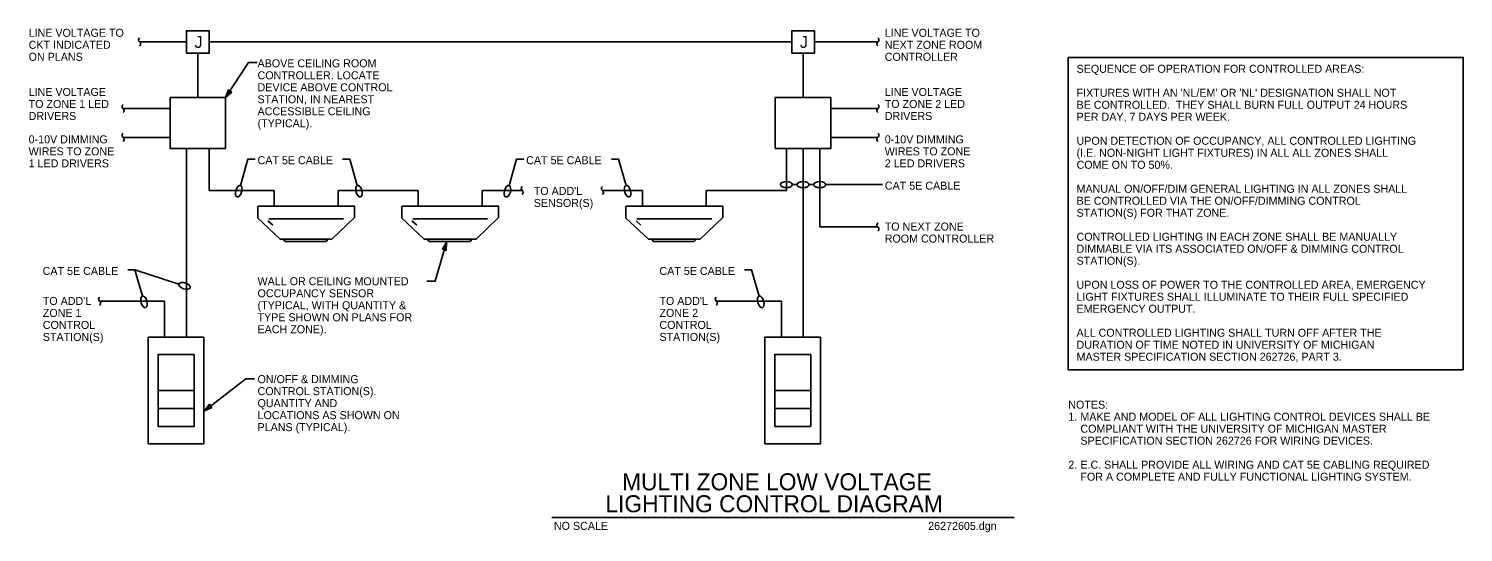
# Model space of a CAD drawing. Extents: x 10121 to 10241, y 10006 to 10048.
import ezdxf

# ---------------------------------------------------------------- set-up
doc = ezdxf.new("R2010")
doc.units = 0
for name, color, linetype in [('G-ANNO-CELL', 7, 'Continuous'), ('G-ANNO-TEXT', 7, 'Continuous'), ('G-DETL-LINE', 7, 'Continuous'), ('Level 3', 7, 'Continuous')]:
    doc.layers.add(name, color=color, linetype=linetype)

msp = doc.modelspace()

# ---------------------------------------------------------------- linework, layer by layer
at = {"layer": 'G-ANNO-CELL'}
msp.add_line((10164.75, 10007.02), (10203.28, 10007.02), dxfattribs=at)
at = {"layer": 'G-ANNO-TEXT'}
for p, q in [((10185.19, 10034.77), (10184.8, 10034.77)), ((10186.58, 10034.77), (10186.19, 10034.77)), ((10192.3, 10034.77), (10187.58, 10034.77)), ((10130.03, 10027.66), (10133.68, 10026.48))]:
    msp.add_line(p, q, dxfattribs=at)
for points in [[(10207.78, 10045.37), (10240.69, 10045.37), (10240.69, 10019.34), (10207.78, 10019.34)], [(10138.09, 10042.49), (10137.58, 10042.03), (10137.82, 10042.67)], [(10155.64, 10029.39), (10155.99, 10029.98), (10155.96, 10029.29)], [(10136.44, 10016.2), (10135.81, 10015.92), (10136.23, 10016.46)]]:
    msp.add_lwpolyline(points, close=True, dxfattribs=at)
for points in [[(10140.21, 10044.94), (10139.48, 10044.94), (10137.58, 10042.03)], [(10140.03, 10036.89), (10139.43, 10036.89), (10138.81, 10034.7)], [(10147.33, 10036.89), (10147.93, 10036.89), (10148.55, 10034.7)], [(10162.41, 10036.89), (10161.81, 10036.89), (10161.19, 10034.7)], [(10169.72, 10036.89), (10170.32, 10036.89), (10170.94, 10034.7)], [(10154.33, 10026.73), (10155.04, 10026.73), (10155.99, 10029.98)], [(10129.42, 10027.66), (10130.03, 10027.66), (10130.65, 10025.47)], [(10180.8, 10027.66), (10181.4, 10027.66), (10182.02, 10025.47)], [(10139.98, 10018.58), (10139.25, 10018.58), (10135.81, 10015.92)]]:
    msp.add_lwpolyline(points, dxfattribs=at)
for centre, major_axis in [((10138.67, 10034.22), (-0.136, -0.481)), ((10148.69, 10034.22), (0.136, -0.481)), ((10161.06, 10034.22), (-0.136, -0.481)), ((10171.07, 10034.22), (0.136, -0.481)), ((10184.3, 10034.77), (-0.5, 0)), ((10185.69, 10034.77), (-0.5, 0)), ((10187.08, 10034.77), (-0.5, 0)), ((10134.16, 10026.33), (0.476, -0.153)), ((10130.78, 10024.99), (0.136, -0.481)), ((10182.16, 10024.99), (0.136, -0.481))]:
    msp.add_ellipse(centre, major_axis=major_axis, ratio=0.5, dxfattribs=at)
at = {"layer": 'G-DETL-LINE'}
for p, q in [((10134.32, 10046.66), (10130.41, 10046.66)), ((10184.75, 10046.66), (10136.2, 10046.66)), ((10186.63, 10046.66), (10191.92, 10046.66)), ((10135.26, 10042.03), (10135.26, 10045.72)), ((10185.69, 10042.03), (10185.69, 10045.72)), ((10132.95, 10041.11), (10129.03, 10041.11)), ((10188.01, 10041.11), (10191.92, 10041.11)), ((10132.95, 10038.71), (10129.03, 10038.71)), ((10188.01, 10038.71), (10191.92, 10038.71)), ((10134.31, 10022.05), (10134.31, 10037.79)), ((10136.21, 10034.29), (10136.21, 10037.79)), ((10184.3, 10034.29), (10184.3, 10037.79)), ((10185.69, 10022.05), (10185.69, 10037.79)), ((10187.08, 10031.24), (10187.08, 10037.79)), ((10136.21, 10034.29), (10141.62, 10034.29)), ((10141.62, 10032.97), (10141.62, 10034.29)), ((10146.95, 10032.97), (10146.95, 10034.29)), ((10146.95, 10034.29), (10153.62, 10034.29)), ((10153.62, 10032.97), (10153.62, 10034.29)), ((10158.95, 10032.97), (10158.95, 10034.29)), ((10162.29, 10034.29), (10158.95, 10034.29)), ((10168.96, 10034.29), (10172.3, 10034.29)), ((10172.3, 10032.97), (10172.3, 10034.29)), ((10177.62, 10034.29), (10184.3, 10034.29)), ((10177.62, 10032.97), (10177.62, 10034.29)), ((10141.5, 10031.38), (10141.1, 10031.74)), ((10141.17, 10031.92), (10144.29, 10031.92)), ((10147.41, 10031.92), (10144.29, 10031.92)), ((10153.5, 10031.38), (10153.1, 10031.74)), ((10153.17, 10031.92), (10156.29, 10031.92)), ((10159.41, 10031.92), (10156.29, 10031.92)), ((10172.17, 10031.38), (10171.77, 10031.74)), ((10171.84, 10031.92), (10174.96, 10031.92)), ((10178.08, 10031.92), (10174.96, 10031.92)), ((10191.92, 10031.24), (10187.08, 10031.24)), ((10132.5, 10025.05), (10127.08, 10025.05)), ((10132.5, 10022.05), (10132.5, 10025.05)), ((10183.88, 10025.05), (10178.46, 10025.05)), ((10183.88, 10022.05), (10183.88, 10025.05)), ((10134.95, 10016.11), (10131.95, 10016.11)), ((10186.33, 10016.11), (10183.33, 10016.11))]:
    msp.add_line(p, q, dxfattribs=at)
for points in [[(10134.32, 10045.72), (10134.32, 10047.6), (10136.2, 10047.6), (10136.2, 10045.72)], [(10184.75, 10045.72), (10184.75, 10047.6), (10186.63, 10047.6), (10186.63, 10045.72)], [(10132.95, 10042.03), (10137.58, 10042.03), (10137.58, 10037.79), (10132.95, 10037.79)], [(10188.01, 10042.03), (10183.37, 10042.03), (10183.37, 10037.79), (10188.01, 10037.79)], [(10135.77, 10022.05), (10131.14, 10022.05), (10131.14, 10013.17), (10135.77, 10013.17)], [(10187.15, 10022.05), (10182.51, 10022.05), (10182.51, 10013.17), (10187.15, 10013.17)], [(10134.95, 10020.61), (10131.95, 10020.61), (10131.95, 10017.61), (10134.95, 10017.61)], [(10186.33, 10020.61), (10183.33, 10020.61), (10183.33, 10017.61), (10186.33, 10017.61)], [(10134.95, 10017.61), (10131.95, 10017.61), (10131.95, 10014.61), (10134.95, 10014.61)], [(10186.33, 10017.61), (10183.33, 10017.61), (10183.33, 10014.61), (10186.33, 10014.61)]]:
    msp.add_lwpolyline(points, close=True, dxfattribs=at)
for points in [[(10140.26, 10032.97), (10148.32, 10032.97), (10148.32, 10032.03), (10146.44, 10030.23), (10142.12, 10030.23), (10140.26, 10031.98), (10140.26, 10032.97)], [(10152.26, 10032.97), (10160.32, 10032.97), (10160.32, 10032.03), (10158.44, 10030.23), (10154.12, 10030.23), (10152.26, 10031.98), (10152.26, 10032.97)], [(10170.93, 10032.97), (10178.99, 10032.97), (10178.99, 10032.03), (10177.11, 10030.23), (10172.8, 10030.23), (10170.93, 10031.98), (10170.93, 10032.97)], [(10146.09, 10030.23), (10146.09, 10030.17), (10145.93, 10030.02), (10142.56, 10030.02), (10142.41, 10030.17), (10142.41, 10030.23)], [(10158.09, 10030.23), (10158.09, 10030.17), (10157.93, 10030.02), (10154.56, 10030.02), (10154.41, 10030.17), (10154.41, 10030.23)], [(10176.76, 10030.23), (10176.76, 10030.17), (10176.6, 10030.02), (10173.24, 10030.02), (10173.08, 10030.17), (10173.08, 10030.23)]]:
    msp.add_lwpolyline(points, dxfattribs=at)
for centre, start, end in [((10130.54, 10046.83), 126.8699, 233.1301), ((10130.29, 10046.5), 306.8699, 53.1301), ((10192.05, 10046.5), 126.8699, 233.1301), ((10191.8, 10046.83), 306.8699, 53.1301), ((10129.16, 10041.27), 126.8699, 233.1301), ((10128.91, 10040.94), 306.8699, 53.1301), ((10192.05, 10040.94), 126.8699, 233.1301), ((10191.8, 10041.27), 306.8699, 53.1301), ((10129.16, 10038.88), 126.8699, 233.1301), ((10128.91, 10038.54), 306.8699, 53.1301), ((10192.05, 10038.54), 126.8699, 233.1301), ((10191.8, 10038.88), 306.8699, 53.1301), ((10162.41, 10034.45), 126.8699, 233.1301), ((10169.09, 10034.45), 126.8699, 233.1301), ((10162.16, 10034.12), 306.8699, 53.1301), ((10168.84, 10034.12), 306.8699, 53.1301), ((10192.05, 10031.41), 126.8699, 233.1301), ((10191.8, 10031.07), 306.8699, 53.1301), ((10127.21, 10025.22), 126.8699, 233.1301), ((10126.96, 10024.88), 306.8699, 53.1301), ((10178.58, 10025.22), 126.8699, 233.1301), ((10178.33, 10024.88), 306.8699, 53.1301)]:
    msp.add_arc(centre, 0.208, start, end, dxfattribs=at)

# ---------------------------------------------------------------- texts
at = {"layer": 'G-ANNO-CELL'}
for s, height, p in [('MULTI ZONE LOW VOLTAGE', 1.4167, (10170.61, 10009.29)), ('LIGHTING CONTROL DIAGRAM', 1.4167, (10169.22, 10007.46)), ('NO SCALE', 0.667, (10164.93, 10005.99))]:
    msp.add_text(s, height=height, dxfattribs=at).set_placement(p)
at = {"layer": 'G-ANNO-TEXT'}
for s, height, p in [('LINE VOLTAGE TO ', 0.6667, (10121.17, 10047.09)), ('LINE VOLTAGE TO ', 0.6667, (10192.49, 10047.09)), ('CKT INDICATED ', 0.6667, (10121.17, 10046.09)), ('NEXT ZONE ROOM ', 0.6667, (10192.49, 10046.09)), ('ON PLANS', 0.667, (10121.17, 10045.09)), ('CONTROLLER', 0.667, (10192.49, 10045.09)), ('ABOVE CEILING ROOM ', 0.6667, (10140.24, 10044.55)), ('CONTROLLER. LOCATE ', 0.6667, (10140.24, 10043.55)), ('SEQUENCE OF OPERATION FOR CONTROLLED AREAS:', 0.6667, (10208.47, 10044.09)), ('DEVICE ABOVE CONTROL ', 0.6667, (10140.24, 10042.55)), ('TO ZONE 1 LED ', 0.6667, (10121.17, 10041.16)), ('LINE VOLTAGE ', 0.6667, (10121.17, 10042.16)), ('STATION, IN NEAREST ', 0.6667, (10140.24, 10041.55)), ('TO ZONE 2 LED ', 0.6667, (10192.49, 10041.16)), ('LINE VOLTAGE ', 0.6667, (10192.49, 10042.16)), ("FIXTURES WITH AN 'NL/EM' OR 'NL' DESIGNATION SHALL NOT ", 0.6667, (10208.47, 10042.09)), ('BE CONTROLLED.  THEY SHALL BURN FULL OUTPUT 24 HOURS ', 0.6667, (10208.47, 10041.09)), ('DRIVERS', 0.667, (10121.17, 10040.16)), ('ACCESSIBLE CEILING ', 0.6667, (10140.24, 10040.55)), ('DRIVERS', 0.667, (10192.49, 10040.16)), ('PER DAY, 7 DAYS PER WEEK.', 0.6667, (10208.47, 10040.09)), ('(TYPICAL).', 0.667, (10140.24, 10039.55)), ('0-10V DIMMING ', 0.6667, (10121.17, 10038.21)), ('0-10V DIMMING ', 0.6667, (10192.49, 10038.21)), ('UPON DETECTION OF OCCUPANCY, ALL CONTROLLED LIGHTING ', 0.6667, (10208.47, 10038.09)), ('WIRES TO ZONE ', 0.6667, (10121.17, 10037.21)), ('CAT 5E CABLE', 0.6667, (10140.24, 10036.47)), ('CAT 5E CABLE', 0.6667, (10162.62, 10036.47)), ('WIRES TO ZONE ', 0.6667, (10192.49, 10037.21)), ('(I.E. NON-NIGHT LIGHT FIXTURES) IN ALL ALL ZONES SHALL ', 0.6667, (10208.47, 10037.09)), ('1 LED DRIVERS ', 0.6667, (10121.17, 10036.21)), ('2 LED DRIVERS ', 0.6667, (10192.49, 10036.21)), ('COME ON TO 50%.', 0.6667, (10208.47, 10036.09)), ("TO ADD'L ", 0.667, (10163.25, 10033.91)), ('CAT 5E CABLE', 0.6667, (10192.5, 10034.35)), ('MANUAL ON/OFF/DIM GENERAL LIGHTING IN ALL ZONES SHALL ', 0.6667, (10208.47, 10034.09)), ('SENSOR(S)', 0.667, (10163.25, 10032.91)), ('BE CONTROLLED VIA THE ON/OFF/DIMMING CONTROL ', 0.6667, (10208.47, 10033.09)), ('STATION(S) FOR THAT ZONE.', 0.6667, (10208.47, 10032.09)), ('TO NEXT ZONE ', 0.6667, (10192.49, 10030.94)), ('ROOM CONTROLLER', 0.6667, (10192.49, 10029.94)), ('CONTROLLED LIGHTING IN EACH ZONE SHALL BE MANUALLY ', 0.6667, (10208.47, 10030.09)), ('DIMMABLE VIA ITS ASSOCIATED ON/OFF & DIMMING CONTROL ', 0.6667, (10208.47, 10029.09)), ('STATION(S).', 0.6667, (10208.47, 10028.09)), ('CAT 5E CABLE', 0.6667, (10122.34, 10027.24)), ('CAT 5E CABLE', 0.6667, (10173.72, 10027.24)), ('WALL OR CEILING MOUNTED ', 0.6667, (10140.24, 10026.38)), ('UPON LOSS OF POWER TO THE CONTROLLED AREA, EMERGENCY ', 0.6667, (10208.47, 10026.09)), ("TO ADD'L ", 0.667, (10122.35, 10024.74)), ('OCCUPANCY SENSOR ', 0.6667, (10140.24, 10025.38)), ('(TYPICAL, WITH QUANTITY & ', 0.6667, (10140.24, 10024.38)), ("TO ADD'L ", 0.667, (10173.72, 10024.74)), ('LIGHT FIXTURES SHALL ILLUMINATE TO THEIR FULL SPECIFIED ', 0.6667, (10208.47, 10025.09)), ('ZONE 1 ', 0.667, (10122.35, 10023.74)), ('TYPE SHOWN ON PLANS FOR ', 0.6667, (10140.24, 10023.38)), ('ZONE 2 ', 0.667, (10173.72, 10023.74)), ('EMERGENCY OUTPUT.', 0.6667, (10208.47, 10024.09)), ('CONTROL ', 0.667, (10122.35, 10022.74)), ('EACH ZONE).', 0.6667, (10140.24, 10022.38)), ('CONTROL ', 0.667, (10173.72, 10022.74)), ('ALL CONTROLLED LIGHTING SHALL TURN OFF AFTER THE ', 0.6667, (10208.47, 10022.09)), ('STATION(S)', 0.667, (10122.35, 10021.74)), ('STATION(S)', 0.667, (10173.72, 10021.74)), ('DURATION OF TIME NOTED IN UNIVERSITY OF MICHIGAN ', 0.6667, (10208.47, 10021.09)), ('MASTER SPECIFICATION SECTION 262726, PART 3.', 0.6667, (10208.47, 10020.09)), ('ON/OFF & DIMMING ', 0.6667, (10140.24, 10018.22)), ('CONTROL STATION(S). ', 0.6667, (10140.24, 10017.22)), ('QUANTITY AND ', 0.6667, (10140.24, 10016.22)), ('NOTES:', 0.667, (10207.78, 10016.09)), ('LOCATIONS AS SHOWN ON ', 0.6667, (10140.24, 10015.22)), ('1.', 0.667, (10207.78, 10015.09)), ('MAKE AND MODEL OF ALL LIGHTING CONTROL DEVICES SHALL BE ', 0.6667, (10208.79, 10015.09)), ('PLANS (TYPICAL).', 0.6667, (10140.24, 10014.22)), ('COMPLIANT WITH THE UNIVERSITY OF MICHIGAN MASTER ', 0.6667, (10208.79, 10014.09)), ('SPECIFICATION SECTION 262726 FOR WIRING DEVICES.', 0.6667, (10208.79, 10013.09)), ('2.', 0.667, (10207.78, 10011.09)), ('E.C. SHALL PROVIDE ALL WIRING AND CAT 5E CABLING REQUIRED ', 0.6667, (10208.79, 10011.09)), ('FOR A COMPLETE AND FULLY FUNCTIONAL LIGHTING SYSTEM.', 0.6667, (10208.79, 10010.09))]:
    msp.add_text(s, height=height, dxfattribs=at).set_placement(p)
at = {"layer": 'G-DETL-LINE'}
for p in [(10134.99, 10046.16), (10185.42, 10046.16)]:
    msp.add_text('J', height=1, dxfattribs=at).set_placement(p)
at = {"layer": 'Level 3'}
msp.add_text('26272605.dgn', height=0.6667, dxfattribs=at).set_placement((10196.11, 10005.99))

doc.saveas('drawing.dxf')
